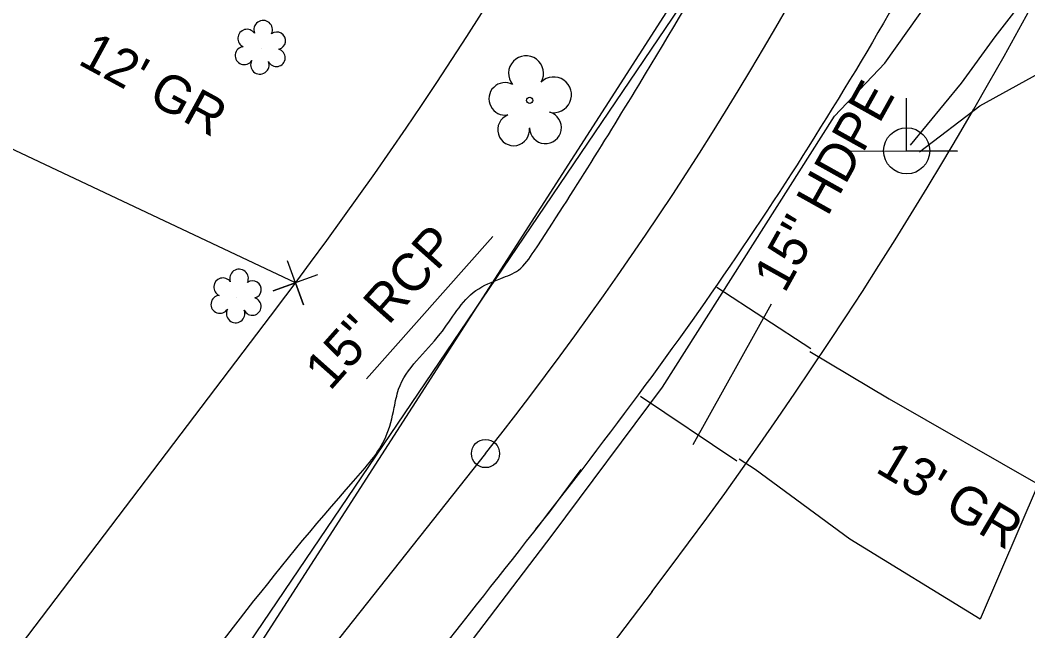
# Model space of a CAD drawing. Extents: x 2089016 to 2094354, y 862840 to 864725.
# Drawn here: x 2091346.4 to 2091453.5, y 863808.3 to 863873.2 of the extents above; entities that cross this region are included whole.
import ezdxf

# ---------------------------------------------------------------- set-up
doc = ezdxf.new("R2010")
doc.units = 0
for name, color, linetype in [('Exist Horizontal Alignment', 7, 'Continuous'), ('Exist Horizontal Alignment Station Label', 7, 'Continuous'), ('Exist Property Corner CELL', 7, 'Continuous'), ('Exist Property Line', 7, 'Continuous'), ('Exist Right of Way Line', 7, 'Continuous'), ('Exist Roads EOP', 7, 'Continuous'), ('Exist Roads Soil', 7, 'Continuous'), ('Exist Roads Soil Text', 7, 'Continuous'), ('Exist Structure Minor Pipes HDPE 15 Inch', 7, 'Continuous'), ('Exist Structure Minor Pipes HDPE 15 Inch Text', 7, 'Continuous'), ('Exist Structure Minor Pipes RCP 15 Inch', 7, 'Continuous'), ('Exist Structure Minor Pipes RCP 15 Inch Text', 7, 'Continuous'), ('Exist Utilities Gas UG Line SUE LOS B', 7, 'Continuous'), ('Exist Utilities Power UG Cable SUE LOS B', 7, 'Continuous'), ('Exist Utilities Sanitary Sewer UG Line', 7, 'Continuous'), ('Exist Utilities Water UG Line SUE LOS C', 7, 'Continuous'), ('Exist Vegetation Shrub CELL', 7, 'Continuous'), ('Exist Vegetation Tree CELL', 7, 'Continuous'), ('Prop SS Fill Line', 7, 'Continuous')]:
    doc.layers.add(name, color=color, linetype=linetype)

msp = doc.modelspace()

# ---------------------------------------------------------------- linework, layer by layer
at = {"layer": 'Exist Horizontal Alignment'}
msp.add_line((2091395.87, 863827.17), (2091352.61, 863772.64), dxfattribs=at)
msp.add_arc((2091098.16, 864063.33), 380, 321.5759, 346.748, dxfattribs=at)
at = {"layer": 'Exist Horizontal Alignment Station Label'}
msp.add_circle((2091395.87, 863827.17), 1.5, dxfattribs=at)
at = {"layer": 'Exist Property Corner CELL'}
msp.add_line((2091375.67, 863845.3), (2091375.67, 863845.3), dxfattribs=at)
msp.add_lwpolyline([(2091378.03, 863846.14), (2091373.32, 863844.46), (2091375.67, 863845.3), (2091376.52, 863842.95), (2091374.83, 863847.65)], dxfattribs=at)
at = {"layer": 'Exist Property Line'}
msp.add_line((2091375.67, 863845.3), (2091172.65, 863941.14), dxfattribs=at)
at = {"layer": 'Exist Right of Way Line'}
for p, q in [((2091373.76, 863842.77), (2091307.39, 863755.46)), ((2091413.57, 863812.51), (2091352.63, 863732.34))]:
    msp.add_line(p, q, dxfattribs=at)
for radius in [444.54, 494.54]:
    msp.add_arc((2091020.08, 864112.07), radius, 322.7135, 346.759, dxfattribs=at)
at = {"layer": 'Exist Roads EOP'}
msp.add_lwpolyline([(2091406, 863825.47), (2091402.66, 863820.99), (2091401.19, 863819.14)], dxfattribs=at)
for points in [[(2090159.86, 864177.45), (2090180.67, 864168.73), (2090222.86, 864151.65), (2090264.39, 864134.6), (2090306, 864117.79), (2090347.24, 864101.05), (2090392.99, 864082.57), (2090433.2, 864065.09), (2090472.83, 864048.96), (2090514.73, 864032.43), (2090559.97, 864014.05), (2090601.37, 863997.19), (2090646.29, 863978.82), (2090688.95, 863961.27), (2090733.38, 863942.96), (2090770.05, 863927.33), (2090814.52, 863908.72), (2090858.91, 863891), (2090901.15, 863874.17), (2090939.87, 863858.28), (2090962.72, 863848.64), (2090997.54, 863834.72), (2091036.07, 863819.08), (2091075.6, 863802.48), (2091112.88, 863787.77), (2091153.64, 863770.65), (2091194.67, 863753.49), (2091234.07, 863737.23), (2091276.57, 863719.33), (2091296.56, 863710.75), (2091332.88, 863695.67), (2091370.71, 863680.05), (2091411.45, 863662.85), (2091427.01, 863655.9), (2091440.19, 863646.8), (2091448.83, 863640.62), (2091463.67, 863633.85), (2091467.99, 863632.17), (2091469.11, 863631.07), (2091469.97, 863630.04), (2091470.37, 863629.28)], [(2091458.63, 863915.3), (2091455.43, 863907.16), (2091438.17, 863872.89), (2091417.82, 863841.31), (2091394.13, 863810.14), (2091368.83, 863778.33), (2091355.6, 863760.48), (2091347.95, 863737.92), (2091353.05, 863717.6), (2091353.04, 863717.56), (2091357.07, 863712.82), (2091361.5, 863708.99), (2091398.61, 863693.57), (2091435.17, 863678.96), (2091472.88, 863664.14), (2091513.07, 863651.42), (2091550.28, 863640.44), (2091559.59, 863639.13), (2091561.17, 863638.35), (2091573.07, 863633.85), (2091588.61, 863630.02), (2091610.92, 863627.57), (2091621.33, 863629.04)], [(2091316.71, 863747.76), (2091320.13, 863750.32), (2091334.11, 863765.12), (2091358.4, 863794.91), (2091381.85, 863824.24), (2091385.28, 863828.95), (2091386.17, 863832.05), (2091386.64, 863833.99), (2091391.05, 863839.87), (2091394.85, 863844.48), (2091397.51, 863845.77), (2091399.36, 863846.66), (2091401.03, 863848.65), (2091412.87, 863867.49), (2091431.95, 863899.97)]]:
    msp.add_spline(points, degree=3, dxfattribs=at)
at = {"layer": 'Exist Roads Soil'}
for p, q in [((2091420.46, 863844.84), (2091430.45, 863838.34)), ((2091422.57, 863826.36), (2091412.35, 863833.24))]:
    msp.add_line(p, q, dxfattribs=at)
msp.add_lwpolyline([(2091430.35, 863837.99), (2091438.77, 863832.97), (2091454.61, 863823.9), (2091448.44, 863809.58), (2091434.6, 863818.09), (2091424.52, 863825.47), (2091422.83, 863826.58)], dxfattribs=at)
at = {"layer": 'Exist Structure Minor Pipes HDPE 15 Inch'}
msp.add_line((2091417.94, 863828.14), (2091426.27, 863843.06), dxfattribs=at)
at = {"layer": 'Exist Structure Minor Pipes RCP 15 Inch'}
msp.add_line((2091383.22, 863835.1), (2091396.64, 863850.21), dxfattribs=at)
at = {"layer": 'Exist Utilities Gas UG Line SUE LOS B'}
msp.add_lwpolyline([(2091490.48, 863668.06), (2091475.98, 863673.49), (2091454.79, 863681.95), (2091442.98, 863687.38), (2091425.45, 863692.47), (2091405.15, 863699.46), (2091382.16, 863707.91), (2091366.11, 863716.32), (2091358.01, 863723.36), (2091353.03, 863739.48), (2091355.82, 863753.41), (2091363.51, 863765.65), (2091372.76, 863777.97), (2091383.66, 863793.16), (2091402.96, 863818.49), (2091414.68, 863834.23), (2091432.96, 863863.02), (2091438.29, 863868.65), (2091446.78, 863880.55)], dxfattribs=at)
at = {"layer": 'Exist Utilities Power UG Cable SUE LOS B'}
for points in [[(2091441.04, 863859.91), (2091446.46, 863866.5), (2091450.03, 863871.44), (2091455.75, 863878.78), (2091461.19, 863884.64), (2091464.88, 863886.3), (2091475.2, 863883.59)], [(2091441.98, 863859.22), (2091448.4, 863864.11), (2091461.32, 863871.21), (2091472.45, 863875.46)]]:
    msp.add_lwpolyline(points, dxfattribs=at)
at = {"layer": 'Exist Utilities Sanitary Sewer UG Line'}
msp.add_lwpolyline([(2091692.13, 864500.83), (2091501.01, 864105.51), (2091469.71, 863953.2), (2091320.59, 863732.95), (2090957.27, 863880.97), (2090681.31, 863994.88), (2090015.26, 864266.1)], dxfattribs=at)
at = {"layer": 'Exist Utilities Water UG Line SUE LOS C'}
msp.add_lwpolyline([(2091311.69, 863687.8), (2091328.33, 863730.1), (2091345.37, 863766.58), (2091360.45, 863789.1), (2091425.86, 863890.78), (2091445.87, 863937.41), (2091455.27, 863961.8)], dxfattribs=at)
at = {"layer": 'Exist Vegetation Shrub CELL'}
for p, q in [((2091372.02, 863870.14), (2091372.02, 863870.14)), ((2091369.45, 863843.72), (2091369.45, 863843.72))]:
    msp.add_line(p, q, dxfattribs=at)
for centre, radius, start, end in [((2091372.25, 863872.18), 0.99, 334.8391, 200.4717), ((2091370.53, 863871.26), 0.968, 35.8908, 245.4216), ((2091373.69, 863871.01), 0.929, 284.4567, 126.0861), ((2091370.22, 863869.43), 0.955, 95.1099, 327.9534), ((2091373.65, 863869.21), 0.937, 204.9913, 73.4601), ((2091371.89, 863868.45), 0.984, 151.2797, 21.387), ((2091369.68, 863845.76), 0.99, 334.8391, 200.4717), ((2091367.97, 863844.85), 0.968, 35.8908, 245.4216), ((2091371.12, 863844.59), 0.929, 284.4567, 126.0861), ((2091367.65, 863843.02), 0.955, 95.1099, 327.9534), ((2091371.09, 863842.79), 0.937, 204.9913, 73.4601), ((2091369.32, 863842.04), 0.984, 151.2797, 21.387)]:
    msp.add_arc(centre, radius, start, end, dxfattribs=at)
at = {"layer": 'Exist Vegetation Tree CELL'}
msp.add_line((2091400.57, 863864.68), (2091400.57, 863864.68), dxfattribs=at)
msp.add_circle((2091400.57, 863864.68), 0.326, dxfattribs=at)
for centre, radius, start, end in [((2091400.18, 863867.56), 1.86, 330.1651, 219.7134), ((2091397.96, 863864.84), 1.73, 62.6636, 279.3457), ((2091403.11, 863865.27), 1.9, 257.1011, 134.1999), ((2091398.86, 863861.56), 1.69, 111.5671, 6.231), ((2091402.24, 863861.79), 1.7, 181.2822, 74.56)]:
    msp.add_arc(centre, radius, start, end, dxfattribs=at)
at = {"layer": 'Prop SS Fill Line'}
msp.add_line((2091440.62, 863859.31), (2091440.62, 863859.31), dxfattribs=at)
msp.add_lwpolyline([(2091434.69, 863859.31), (2091446.02, 863859.27), (2091440.62, 863859.29), (2091440.62, 863864.93)], dxfattribs=at)
msp.add_circle((2091440.63, 863859.32), 2.45, dxfattribs=at)

# ---------------------------------------------------------------- texts
at = {"layer": 'Exist Roads Soil Text'}
for s, rotation, p in [("12' GR", 331.4313, (2091352.43, 863868.61)), ("13' GR", 329.2492, (2091437.17, 863825.29))]:
    msp.add_text(s, height=4, rotation=rotation, dxfattribs=at).set_placement(p)
at = {"layer": 'Exist Structure Minor Pipes HDPE 15 Inch Text'}
msp.add_text('15" HDPE', height=4, rotation=60.8349, dxfattribs=at).set_placement((2091427.66, 863844.1))
at = {"layer": 'Exist Structure Minor Pipes RCP 15 Inch Text'}
msp.add_text('15" RCP', height=4, rotation=48.3908, dxfattribs=at).set_placement((2091379.35, 863833.73))

doc.saveas('drawing.dxf')
